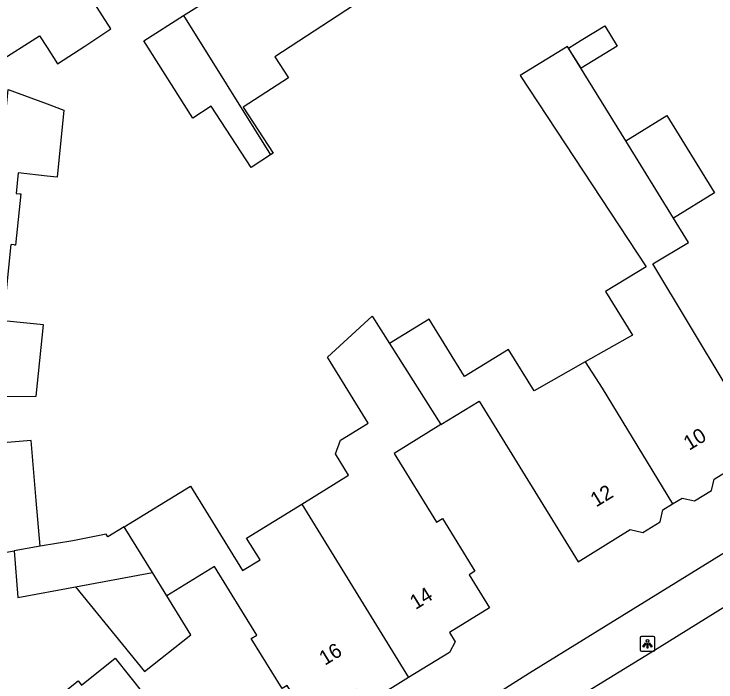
# Model space of a CAD drawing. Extents: x 161354 to 161876, y 382161 to 382804.
# Drawn here: x 161497.74 to 161545.72, y 382343.81 to 382389.46 of the extents above; entities that cross this region are included whole.
import ezdxf

# ---------------------------------------------------------------- set-up
doc = ezdxf.new("R2010")
doc.units = 0
for name, color, linetype in [('IMGEO_Lichtpunt', 7, 'Continuous'), ('IMGEO_Pand', 7, 'Continuous'), ('IMGEO_Pand_nummerreeks', 7, 'Continuous'), ('IMGEO_Pand_vergunning_verleend', 7, 'Continuous'), ('IMGEO_Rijbaan_lokaal_open', 7, 'Continuous'), ('IMGEO_Voetpad_open', 7, 'Continuous')]:
    doc.layers.add(name, color=color, linetype=linetype)

msp = doc.modelspace()

# ---------------------------------------------------------------- linework, layer by layer
at = {"layer": 'IMGEO_Lichtpunt'}
for p, q in [((161541.438, 382346.914), (161540.63, 382346.914)), ((161541.438, 382346.914), (161540.63, 382346.914)), ((161540.536, 382346.819), (161540.536, 382346.012)), ((161540.536, 382346.819), (161540.536, 382346.012)), ((161541.532, 382346.012), (161541.532, 382346.819)), ((161541.532, 382346.012), (161541.532, 382346.819)), ((161540.63, 382345.918), (161541.438, 382345.918)), ((161540.63, 382345.918), (161541.438, 382345.918))]:
    msp.add_line(p, q, dxfattribs=at)
for points in [[(161540.91, 382346.483), (161540.949, 382346.455), (161540.761, 382346.193), (161540.723, 382346.22), (161540.91, 382346.483)], [(161541.012, 382346.435), (161541.059, 382346.435), (161541.059, 382346.113), (161541.012, 382346.113), (161541.012, 382346.435)], [(161541.122, 382346.455), (161541.16, 382346.482), (161541.347, 382346.22), (161541.308, 382346.192), (161541.122, 382346.455)]]:
    msp.add_lwpolyline(points, dxfattribs=at)
msp.add_circle((161541.035, 382346.617), 0.0994, dxfattribs=at)
for centre, start, end in [((161540.63, 382346.819), 90, 180), ((161540.63, 382346.819), 90, 180), ((161541.438, 382346.819), 0, 90), ((161541.438, 382346.819), 0, 90), ((161540.63, 382346.012), 180, 270), ((161540.63, 382346.012), 180, 270), ((161541.438, 382346.012), 270, 0), ((161541.438, 382346.012), 270, 360)]:
    msp.add_arc(centre, 0.0946, start, end, dxfattribs=at)
at = {"layer": 'IMGEO_Pand'}
for points in [[(161509.32, 382389.352), (161512.6, 382391.441), (161509.593, 382396.047), (161509.184, 382395.787), (161506.919, 382399.254), (161507.325, 382399.519), (161505.795, 382401.862), (161508.864, 382403.867), (161508.335, 382404.677), (161511.322, 382406.629)], [(161503.137, 382392.692), (161500.681, 382396.546), (161500, 382396.112), (161498.783, 382395.337), (161496.857, 382398.36), (161491.166, 382394.735), (161493.735, 382390.704), (161493.078, 382390.285), (161495.731, 382386.121), (161496.289, 382386.477), (161496.532, 382386.095), (161499.482, 382387.974), (161500, 382387.174), (161500.724, 382386.056), (161502.582, 382387.27), (161504.368, 382388.437), (161502.083, 382392.021), (161503.137, 382392.692)], [(161518.906, 382394.901), (161521.755, 382390.401), (161521.54, 382390.261), (161521.458, 382390.387), (161515.571, 382386.54), (161516.508, 382385.107), (161513.409, 382383.081), (161515.452, 382379.955), (161515.259, 382379.829)], [(161515.259, 382379.829), (161513.941, 382378.968), (161511.207, 382383.152), (161509.972, 382382.345), (161506.604, 382387.621), (161509.32, 382389.352)], [(161509.32, 382389.352), (161515.259, 382379.829)], [(161539.552, 382380.789), (161535.645, 382387.132), (161535.578, 382387.241), (161532.345, 382385.251), (161540.939, 382372.189), (161538.171, 382370.485), (161540.006, 382367.505), (161536.787, 382365.679)], [(161486.324, 382374.818), (161486.734, 382378.916), (161486.978, 382378.892), (161487.322, 382382.33), (161490.457, 382382.017), (161490.488, 382382.326), (161494.22, 382381.953), (161494.183, 382381.583), (161497.046, 382381.288), (161497.352, 382384.306), (161500, 382383.308), (161501.136, 382382.88), (161500.691, 382378.312), (161500, 382378.387), (161498.033, 382378.6), (161497.892, 382377.195), (161498.144, 382377.168), (161498.203, 382377.162), (161497.852, 382373.665), (161497.793, 382373.671), (161497.741, 382373.676), (161497.542, 382373.696)], [(161539.552, 382380.789), (161542.362, 382382.519), (161545.615, 382377.241), (161542.804, 382375.51)], [(161542.804, 382375.51), (161539.552, 382380.789)], [(161542.751, 382355.974), (161543.409, 382356.379), (161544.243, 382356.181), (161545.408, 382356.898), (161545.591, 382357.669), (161548.998, 382359.767), (161541.411, 382372.389), (161543.83, 382373.843), (161542.804, 382375.51)], [(161486.324, 382374.818), (161485.914, 382370.72), (161486.198, 382370.692), (161485.86, 382367.313), (161488.922, 382367.007), (161488.905, 382366.837), (161492.712, 382366.457), (161492.736, 382366.691), (161495.599, 382366.388), (161495.296, 382363.317), (161499.257, 382363.337), (161499.745, 382368.221), (161497.022, 382368.493), (161497.542, 382373.696)], [(161517.407, 382355.965), (161520.609, 382357.937), (161519.714, 382359.39), (161520.065, 382360.343), (161520.868, 382360.838), (161521.941, 382361.498), (161519.162, 382366.01), (161522.21, 382368.807), (161523.396, 382366.941)], [(161536.787, 382365.679), (161533.288, 382363.694), (161531.537, 382366.537), (161528.524, 382364.681), (161526.105, 382368.609), (161523.396, 382366.941)], [(161523.396, 382366.941), (161526.913, 382361.399)], [(161536.787, 382365.679), (161537.934, 382363.884), (161542.751, 382355.974)], [(161526.913, 382361.399), (161529.524, 382363.007), (161536.289, 382352.023), (161539.857, 382354.22), (161540.709, 382354.017), (161541.897, 382354.749), (161542.092, 382355.568), (161542.751, 382355.974)], [(161526.913, 382361.399), (161523.711, 382359.427), (161526.606, 382354.727), (161527.02, 382354.982), (161529.239, 382351.379), (161528.839, 382351.133), (161530.233, 382348.869), (161527.506, 382347.19), (161527.899, 382346.551), (161527.504, 382345.82), (161524.713, 382344.101)], [(161499.52, 382353.085), (161499.257, 382356.205), (161498.911, 382360.315), (161496.711, 382360.131), (161496.653, 382360.502), (161490.935, 382360.023), (161485.952, 382359.604), (161486.037, 382358.585), (161485.408, 382357.84), (161485.507, 382356.655), (161486.255, 382356.023), (161486.61, 382351.797), (161489.441, 382352.035), (161489.468, 382351.71), (161493.453, 382352.045), (161493.425, 382352.37), (161497.358, 382352.698), (161497.75, 382352.769)], [(161505.273, 382354.418), (161509.811, 382357.184), (161513.362, 382351.416), (161514.557, 382352.152), (161513.638, 382353.644), (161517.407, 382355.965)], [(161517.407, 382355.965), (161524.713, 382344.101)], [(161505.273, 382354.418), (161504.147, 382353.731), (161504.044, 382353.9), (161501.753, 382353.46), (161499.52, 382353.085)], [(161507.196, 382351.29), (161505.273, 382354.418)], [(161499.52, 382353.085), (161497.752, 382352.769), (161497.75, 382352.769)], [(161497.75, 382352.769), (161498.009, 382349.575), (161501.933, 382350.307)], [(161524.713, 382344.101), (161522.412, 382342.684), (161521.578, 382342.66), (161521.185, 382343.298), (161517.835, 382341.235), (161516.401, 382343.565), (161516.059, 382343.354), (161513.953, 382346.775), (161514.328, 382347.006), (161511.435, 382351.707), (161508.174, 382349.7)], [(161501.933, 382350.307), (161507.196, 382351.29)], [(161508.174, 382349.7), (161507.196, 382351.29)], [(161501.933, 382350.307), (161506.662, 382344.526), (161509.821, 382347.027), (161508.174, 382349.7)], [(161498.649, 382341.115), (161498.885, 382341.304), (161499.745, 382341.991), (161500, 382342.195), (161502.125, 382343.894), (161502.363, 382343.594), (161504.663, 382345.427), (161508.575, 382340.519), (161511.691, 382336.608), (161508.532, 382334.091), (161508.385, 382332.789), (161507.808, 382332.33), (161506.507, 382332.477), (161505.918, 382332.008)]]:
    msp.add_lwpolyline(points, dxfattribs=at)
at = {"layer": 'IMGEO_Pand_vergunning_verleend'}
msp.add_lwpolyline([(161535.645, 382387.132), (161536.51, 382387.664), (161538.114, 382388.651), (161538.963, 382387.271), (161536.495, 382385.754), (161535.645, 382387.132)], dxfattribs=at)
at = {"layer": 'IMGEO_Rijbaan_lokaal_open'}
msp.add_lwpolyline([(161522.13, 382334.077), (161529.654, 382338.671), (161533.737, 382341.207), (161541.227, 382345.802), (161546.313, 382348.96), (161550.162, 382351.34)], dxfattribs=at)
at = {"layer": 'IMGEO_Voetpad_open'}
msp.add_lwpolyline([(161617.144, 382396.335), (161578.374, 382372.283), (161567.929, 382365.979), (161532.97, 382344.41), (161519.365, 382335.787), (161506.91, 382326.302), (161500, 382320.746), (161495.67, 382317.265)], dxfattribs=at)

# ---------------------------------------------------------------- texts
at = {"layer": 'IMGEO_Pand_nummerreeks'}
for s, rotation, p in [('10', 31.3553, (161543.884, 382359.601)), ('12', 31.3553, (161537.524, 382355.726)), ('14', 31.6215, (161525.186, 382348.72)), ('16', 31.6225, (161518.987, 382344.904))]:
    msp.add_text(s, height=1, rotation=rotation, dxfattribs=at).set_placement(p)

doc.saveas('drawing.dxf')
